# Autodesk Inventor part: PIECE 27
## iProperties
Created: 2004-11
Part Number: PIECE 27
Document SubType Name: Modeling
Designer: Bruno
Manufacturer: Standard
Standards Organization: Custom
Author: Bruno
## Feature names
1. Base1
